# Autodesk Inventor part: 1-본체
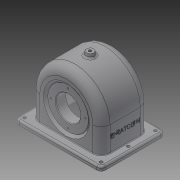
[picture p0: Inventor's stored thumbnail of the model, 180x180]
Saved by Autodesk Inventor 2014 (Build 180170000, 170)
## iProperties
Created: 2015-09
Part Number: 1-본체
Material: 일반
Document SubType Name: Modeling
Designer: Administrator
Density: 1 g/cm^3
Appearance: 기본값
Author: Administrator
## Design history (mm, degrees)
sketch "스케치2"
  geometry: L1 (57, 0)-(57, 47); L2 (-57, 47)-(-57, 0); L3 (-57, 0)-(57, 0); A1 r 57 centre (0, 47) between (57, 47) and (-57, 47); 1 further point
  constraints: 6 end point, 2 point on circle, 2 tangent, 1 centre point, 1 midpoint, 1 parallel, 1 perpendicular, 1 vertical, 1 vertical alignment
  dimensions: "d0" = 47 distance of A1.centre point (0, 0); "d1" = 57 radius of A1
extrude "돌출1" new body sketch "스케치2" distance "d2" = 38.5; taper "d3" = 0 deg
sketch "스케치4"
  geometry: L1 (70, -7)-(-70, -7); L2 (-70, -7)-(-70, 0); L3 (-70, 0)-(70, 0); L4 (70, 0)-(70, -7); L5 (57, 0)-(-57, 0) reference; 3 further points
  constraints: 8 end point, 2 midpoint, 2 parallel, 1 collinear, 1 horizontal, 1 perpendicular, 1 vertical alignment
  dimensions: "d6" = 7 distance of L1.end L2.end; "d7" = 140 distance of L2.end L3.end
extrude "돌출2" join sketch "스케치4" distance "d8" = 52; taper "d9" = 0 deg
sketch "스케치5"
  geometry: L1 (51, 0)-(51, -47); L2 (-51, -47)-(-51, 0); L3 (-51, 0)-(51, 0); L4 (-70, 0)-(70, 0) reference; L5 (57, -47)-(57, -7) reference; A1 r 51 centre (0, -47) between (-51, -47) and (51, -47); A2 r 57 centre (0, -47) between (-57, -47) and (57, -47) reference; 1 further point
  constraints: 6 end point, 2 point on circle, 2 tangent, 1 centre point, 1 collinear, 1 concentric, 1 parallel, 1 perpendicular, 1 vertical
  dimensions: "d10" = 6 distance between parallel lines of L5 L1
extrude "돌출3" cut sketch "스케치5" distance "d11" = 33.5; taper "d12" = 0 deg
sketch "스케치6"
  geometry: L1 (-33.5, 47)-(-33.5, 86.747); L2 (-33.5, 86.747)-(-19.5, 75); L3 (-19.5, 75)-(-19.5, 47); L4 (-19.5, 47)-(-33.5, 47); L5 (33.5, 0)-(-33.5, 0) reference; L6 (-33.5, 98)-(-33.5, 47) reference; L7 (-38.5, 104)-(-38.5, 47) reference; 1 further point
  constraints: 8 end point, 1 collinear, 1 parallel, 1 perpendicular, 1 vertical
  dimensions: "d13" = 47 distance between parallel lines of L4 L5; "d14" = 56 diameter of L2.end L4; "d15" = 50 deg angle of L2 L3; "d16" = 19 distance between parallel lines of L3 L7
revolve "회전1" sketch "스케치6" stored, may be unused: angle "d17" = 90 deg
sketch "스케치7"
  geometry: C1 r 31 at (0, 0); A1 r 57 centre (0, 0) between (-57, 0) and (57, 0) reference; 1 further point
  constraints: 1 centre point, 1 concentric
  dimensions: "d18" = 62 diameter of C1
extrude "돌출4" join sketch "스케치7" distance "d19" = 10; taper "d20" = 0 deg
node "작업 평면2"
  node "작업 평면1"
sketch "스케치9"
  geometry: C1 r 6 at (0, 0); 1 further point
  constraints: 1 centre point, 1 coincident
  dimensions: "d22" = 12 diameter of C1
extrude "돌출5" join sketch "스케치9" stored distance "d23" = 10; taper "d24" = 10 deg
sketch "스케치12"
  geometry: L1 (-38.5, 84.416)-(-38.5, 47); L2 (-38.5, 47)-(-35.5, 47); L3 (-35.5, 47)-(-35.5, 80); L4 (-35.5, 80)-(-33.237, 80); L5 (-33.237, 80)-(-38.5, 84.416); L6 (-38.5, 104)-(-38.5, 47) reference; L7 (-33.5, 86.747)-(-19.5, 75) reference; 1 further point
  constraints: 10 end point, 3 parallel, 1 collinear, 1 perpendicular, 1 vertical
  dimensions: "d34" = 47 distance from line of L2 point (0, 0); "d35" = 5 distance between parallel lines of L5 L7; "d36" = 66 diameter of L4 L2; "d37" = 3 distance between parallel lines of L1 L3
revolve "회전2" sketch "스케치12" stored, may be unused: angle "d38" = 90 deg
sketch "스케치13"
  geometry: L1 (0, 47)-(0, 0)
  constraints: 2 end point, 1 vertical
  dimensions: "d39" = 47 distance of L1.start L1.end
hole "구멍2" sketch "스케치13" at (0, 0) diameter "d40" = 40; stored, may be unused: countersink angle "d44" = 90 deg, drill point angle "d46" = 0 deg; dims "d41" = 6, "d42" = 4, "d43" = 2, "d45" = 3
hole "구멍3" diameter "d49" = 4.459; stored, may be unused: countersink angle "d53" = 90 deg, drill point angle "d55" = 0 deg; dims "d50" = 20, "d51" = 4, "d52" = 2, "d54" = 10, "d58" = 10, "d59" = 10
sketch "스케치14"
  geometry: L1 (0, -47)-(0, 0); L2 (0, 0)-(0, 28)
  constraints: 4 end point, 1 collinear, 1 vertical
  dimensions: "d56" = 47 distance of L1.start L1.end; "d57" = 28 distance of L1.end L2.end
hole "구멍4" sketch "스케치14" at (0, 28) diameter "d60" = 2.459; stored, may be unused: countersink angle "d64" = 90 deg, drill point angle "d66" = 118 deg; dims "d61" = 7, "d62" = 4, "d63" = 2, "d65" = 9
sketch "스케치15"
  geometry: L1 (0, 47)-(0, 0); L2 (0, 0)-(0, -24)
  constraints: 4 end point, 1 collinear, 1 vertical
  dimensions: "d70" = 47 distance of L1.start L1.end; "d71" = 24 distance of L1.end L2.end
hole "구멍5" sketch "스케치15" at (0, -24) diameter "d72" = 2.459; stored, may be unused: countersink angle "d76" = 90 deg, drill point angle "d78" = 118 deg; dims "d73" = 6, "d74" = 4, "d75" = 2, "d77" = 8
fillet "모깎기1" dims "d82" = 7
sketch "스케치16"
  geometry: L1 (63, 52)-(1, 52); L2 (1, 52)-(1, 8); L3 (1, 52)-(1, 96)
  constraints: 6 end point, 1 collinear, 1 horizontal, 1 perpendicular
  dimensions: "d83" = 62 distance of L1.start L1.end; "d84" = 44 distance of L1.end L2.end; "d85" = 44 distance of L1.end L3.end
hole "구멍6" sketch "스케치16" diameter "d86" = 5; stored, may be unused: countersink angle "d90" = 90 deg, drill point angle "d92" = 0 deg; dims "d87" = 5, "d88" = 4, "d89" = 2, "d91" = 8
hole "구멍7" sketch "스케치16" diameter "d93" = 5; stored, may be unused: countersink angle "d97" = 90 deg, drill point angle "d99" = 0 deg; dims "d94" = 5, "d95" = 4, "d96" = 2, "d98" = 8
hole "구멍8" sketch "스케치16" diameter "d100" = 5; stored, may be unused: countersink angle "d104" = 90 deg, drill point angle "d106" = 0 deg; dims "d101" = 5, "d102" = 4, "d103" = 2, "d105" = 8
fillet "모깎기2" dims "d107" = 14
fillet "모깎기3" dims "d108" = 9
chamfer "모따기1" distance "d109" = 1; stored, may be unused: second distance "d110" = 2, angle "d111" = 45 deg
fillet "모깎기4" dims "d112" = 3
fillet "모깎기5" dims "d113" = 1
fillet "모깎기6" dims "d114" = 0.5
fillet "모깎기7" dims "d115" = 3
fillet "모깎기8" dims "d116" = 3
sketch "스케치17"
  geometry: L1 (13.398, -17.573)-(13.398, 66.573); L2 (13.398, 66.573)-(20.602, 66.573); L3 (20.602, 66.573)-(20.602, -17.573); L4 (20.602, -17.573)-(13.398, -17.573); L5 (47, 69.5)-(47, -20.5) reference; L6 (0, -14)-(39, -14) reference; 4 further points
  constraints: 3 midpoint, 1 horizontal alignment, 2 other
  dimensions: "d117" = 30 distance from line of L5 point (17, -17.573); "d118" = 38.5 distance from line of L6 point (20.602, 24.5) (derived)
feature "엠보싱1" sketch "스케치17" dims "d10" = 6, "d119" = 0.5, "d120" = 0
node "솔리드1"
mirror "대칭1"
pattern_circular "원형 패턴1" dims angle "d68" = 360 deg
pattern_circular "원형 패턴2" dims angle "d80" = 360 deg
mirror "대칭2"
other parameters: "d21" = 6
